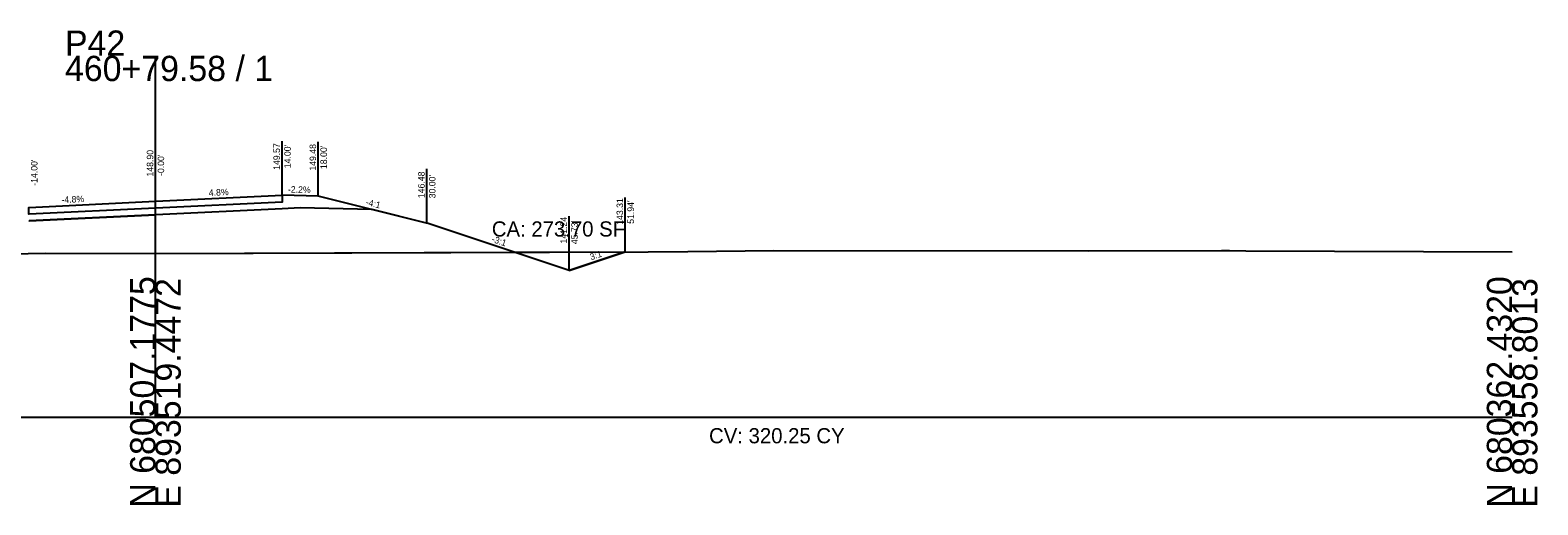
# Model space of a CAD drawing. Extents: x -26 to 4403, y -13 to 9578.
# Drawn here: x 1236.1 to 1402.8, y 990.3 to 1042.8 of the extents above; entities that cross this region are included whole.
import ezdxf

# ---------------------------------------------------------------- set-up
doc = ezdxf.new("R2010")
doc.units = 0
for name, color, linetype in [('_CIVIL_CONSTRUCTION', 7, 'Continuous'), ('CONST_DCH', 7, 'Continuous'), ('CONST_LV3', 7, 'Continuous'), ('DTM_CORRIDOR', 7, 'Continuous'), ('DTM_TEMP_DROP', 7, 'Continuous'), ('DTM_X_GROUND', 7, 'Continuous'), ('SLOPE_STAKES_FILL', 7, 'Continuous'), ('XS_CELL', 7, 'Continuous'), ('XS_M_SHAPES_EARTHWORK', 7, 'Continuous'), ('XS_P_ASPHALT', 7, 'Continuous'), ('XS_P_GROUND', 7, 'Continuous'), ('XS_P_SHOULDER', 7, 'Continuous'), ('XS_P_SUBGRADE_GRANULAR', 7, 'Continuous'), ('XS_P_TX_CLEARZONE', 7, 'Continuous'), ('XS_P_TX_FS_BS', 7, 'Continuous'), ('XS_SHEET_EW_TX_AREA', 7, 'Continuous'), ('XS_SHEET_EW_TX_VOLUME', 7, 'Continuous')]:
    doc.layers.add(name, color=color, linetype=linetype)

msp = doc.modelspace()

# ---------------------------------------------------------------- linework, layer by layer
at = {"layer": 'CONST_LV3'}
msp.add_lwpolyline([(1280, 1021.48), (1279.98, 1021.49), (1273.96, 1022.99)], dxfattribs=at)
at = {"layer": 'DTM_X_GROUND'}
msp.add_lwpolyline([(1205.86, 1017.54), (1237.81, 1018.17), (1249.9, 1018.11), (1304.48, 1018.32), (1308.85, 1018.36), (1318.36, 1018.46), (1353.16, 1018.41), (1367.85, 1018.45), (1368.76, 1018.44), (1370.55, 1018.43), (1400, 1018.3)], dxfattribs=at)
at = {"layer": 'XS_CELL'}
for p, q in [((1250, 1000), (1250, 1040)), ((1000, 1000), (1250, 1000)), ((1250, 1000), (1400, 1000))]:
    msp.add_line(p, q, dxfattribs=at)
at = {"layer": 'XS_M_SHAPES_EARTHWORK'}
msp.add_lwpolyline([(1205.86, 1017.54), (1237.81, 1018.17), (1249.9, 1018.11), (1289.67, 1018.26), (1280.04, 1021.47), (1280, 1021.48), (1279.98, 1021.49), (1279.97, 1021.49), (1273.96, 1022.99), (1273.94, 1022.99), (1266, 1023.17), (1264.01, 1023.07), (1264, 1023.07), (1250.04, 1022.4), (1250, 1022.4), (1236.04, 1021.73)], dxfattribs=at)
msp.add_lwpolyline([(1289.67, 1018.26), (1301.94, 1018.31), (1295.73, 1016.24)], close=True, dxfattribs=at)
at = {"layer": 'XS_P_ASPHALT'}
msp.add_lwpolyline([(1236.04, 1023.23), (1250, 1023.9), (1250.04, 1023.9), (1264, 1024.57), (1264, 1023.82), (1264, 1023.82), (1250.04, 1023.15), (1250, 1023.15), (1236.04, 1022.48), (1236, 1022.48), (1236, 1022.48), (1236, 1023.23), (1236.04, 1023.23)], dxfattribs=at)
at = {"layer": 'XS_P_GROUND'}
for points in [[(1295.73, 1016.24), (1280.04, 1021.47), (1280, 1021.48), (1279.97, 1021.49), (1268, 1024.48)], [(1295.73, 1016.24), (1301.94, 1018.31)]]:
    msp.add_lwpolyline(points, dxfattribs=at)
at = {"layer": 'XS_P_SHOULDER'}
msp.add_lwpolyline([(1268, 1024.48), (1267.99, 1024.48), (1264, 1024.57)], dxfattribs=at)
at = {"layer": 'XS_P_SUBGRADE_GRANULAR'}
for points in [[(1236, 1021.73), (1236.04, 1021.73), (1250, 1022.4)], [(1264, 1023.07), (1250.04, 1022.4), (1250, 1022.4)], [(1273.96, 1022.99), (1273.94, 1022.99), (1266, 1023.17), (1264.01, 1023.07), (1264, 1023.07)]]:
    msp.add_lwpolyline(points, dxfattribs=at)
at = {"layer": 'XS_P_TX_CLEARZONE'}
for p, q in [((1264, 1024.57), (1264, 1030.57)), ((1264, 1024.57), (1264, 1030.57)), ((1264, 1024.57), (1264, 1030.57)), ((1264, 1024.57), (1264, 1030.57)), ((1264, 1024.57), (1264, 1030.57)), ((1264, 1024.57), (1264, 1030.57)), ((1268, 1024.48), (1268, 1030.48)), ((1268, 1024.48), (1268, 1030.48)), ((1268, 1024.48), (1268, 1030.48)), ((1268, 1024.48), (1268, 1030.48)), ((1268, 1024.48), (1268, 1030.48)), ((1268, 1024.48), (1268, 1030.48)), ((1250, 1023.9), (1250, 1029.9)), ((1250, 1023.9), (1250, 1029.9)), ((1250, 1023.9), (1250, 1029.9)), ((1250, 1023.9), (1250, 1029.9)), ((1250, 1023.9), (1250, 1029.9)), ((1250, 1023.9), (1250, 1029.9)), ((1280, 1021.48), (1280, 1027.48)), ((1280, 1021.48), (1280, 1027.48)), ((1280, 1021.48), (1280, 1027.48)), ((1301.94, 1018.31), (1301.94, 1024.31)), ((1301.94, 1018.31), (1301.94, 1024.31)), ((1301.94, 1018.31), (1301.94, 1024.31)), ((1301.94, 1018.31), (1301.94, 1024.31)), ((1301.94, 1018.31), (1301.94, 1024.31)), ((1301.94, 1018.31), (1301.94, 1024.31)), ((1295.73, 1016.24), (1295.73, 1022.24)), ((1295.73, 1016.24), (1295.73, 1022.24)), ((1295.73, 1016.24), (1295.73, 1022.24)), ((1295.73, 1016.24), (1295.73, 1022.24)), ((1295.73, 1016.24), (1295.73, 1022.24)), ((1295.73, 1016.24), (1295.73, 1022.24))]:
    msp.add_line(p, q, dxfattribs=at)

# ---------------------------------------------------------------- texts
at = {"layer": '_CIVIL_CONSTRUCTION'}
for p in [(1249.96, 1023.84), (1263.96, 1024.51)]:
    msp.add_text('X', height=0.12, dxfattribs=at).set_placement(p)
at = {"layer": 'CONST_DCH'}
msp.add_text('X', height=0.12, dxfattribs=at).set_placement((1295.69, 1016.18))
at = {"layer": 'DTM_CORRIDOR'}
msp.add_text('X', height=0.12, dxfattribs=at).set_placement((1301.9, 1018.25))
at = {"layer": 'DTM_TEMP_DROP'}
msp.add_text('X', height=0.12, dxfattribs=at).set_placement((1267.96, 1024.42))
at = {"layer": 'SLOPE_STAKES_FILL'}
msp.add_text('X', height=0.12, dxfattribs=at).set_placement((1279.96, 1021.42))
at = {"layer": 'XS_CELL'}
for s, p in [('P42', (1240, 1040)), ('460+79.58 / 1', (1240, 1037.2))]:
    msp.add_text(s, height=2.8, dxfattribs=at).set_placement(p)
for s, p in [('N 680507.1775', (1250, 990)), ('E 893519.4472', (1252.8, 990)), ('N 680362.4320', (1400, 990)), ('E 893558.8013', (1402.8, 990))]:
    msp.add_text(s, height=2.8, rotation=90, dxfattribs=at).set_placement(p)
at = {"layer": 'XS_P_TX_CLEARZONE'}
for s, p in [('149.57', (1263.76, 1027.38)), ('149.57', (1263.76, 1027.38)), ('149.57', (1263.76, 1027.38)), ('149.57', (1263.76, 1027.38)), ('149.57', (1263.76, 1027.38)), ('149.57', (1263.76, 1027.38)), ('149.48', (1267.76, 1027.29)), ('149.48', (1267.76, 1027.29)), ('149.48', (1267.76, 1027.29)), ('149.48', (1267.76, 1027.29)), ('149.48', (1267.76, 1027.29)), ('149.48', (1267.76, 1027.29)), ('148.90', (1249.76, 1026.64)), ('148.90', (1249.76, 1026.64)), ('148.90', (1249.76, 1026.64)), ('148.90', (1249.76, 1026.64)), ('148.90', (1249.76, 1026.64)), ('148.90', (1249.76, 1026.64)), ("-0.00'", (1250.96, 1026.7)), ("-0.00'", (1250.96, 1026.7)), ("-0.00'", (1250.96, 1026.7)), ("-0.00'", (1250.96, 1026.7)), ("-0.00'", (1250.96, 1026.7)), ("-0.00'", (1250.96, 1026.7)), ("14.00'", (1264.96, 1027.56)), ("14.00'", (1264.96, 1027.56)), ("14.00'", (1264.96, 1027.56)), ("14.00'", (1264.96, 1027.56)), ("14.00'", (1264.96, 1027.56)), ("14.00'", (1264.96, 1027.56)), ("18.00'", (1268.96, 1027.47)), ("18.00'", (1268.96, 1027.47)), ("18.00'", (1268.96, 1027.47)), ("18.00'", (1268.96, 1027.47)), ("18.00'", (1268.96, 1027.47)), ("18.00'", (1268.96, 1027.47)), ("-14.00'", (1236.96, 1025.62)), ("-14.00'", (1236.96, 1025.62)), ("-14.00'", (1236.96, 1025.62)), ("-14.00'", (1236.96, 1025.62)), ("-14.00'", (1236.96, 1025.62)), ("-14.00'", (1236.96, 1025.62)), ('146.48', (1279.76, 1024.25)), ('146.48', (1279.76, 1024.25)), ('146.48', (1279.76, 1024.25)), ("30.00'", (1280.96, 1024.23)), ("30.00'", (1280.96, 1024.23)), ("30.00'", (1280.96, 1024.23)), ('143.31', (1301.7, 1021.3)), ('143.31', (1301.7, 1021.3)), ('143.31', (1301.7, 1021.3)), ('143.31', (1301.7, 1021.3)), ('143.31', (1301.7, 1021.3)), ('143.31', (1301.7, 1021.3)), ("51.94'", (1302.9, 1021.41)), ("51.94'", (1302.9, 1021.41)), ("51.94'", (1302.9, 1021.41)), ("51.94'", (1302.9, 1021.41)), ("51.94'", (1302.9, 1021.41)), ("51.94'", (1302.9, 1021.41)), ('141.24', (1295.49, 1019.23)), ('141.24', (1295.49, 1019.23)), ('141.24', (1295.49, 1019.23)), ('141.24', (1295.49, 1019.23)), ('141.24', (1295.49, 1019.23)), ('141.24', (1295.49, 1019.23)), ("45.73'", (1296.69, 1019.16)), ("45.73'", (1296.69, 1019.16)), ("45.73'", (1296.69, 1019.16)), ("45.73'", (1296.69, 1019.16)), ("45.73'", (1296.69, 1019.16)), ("45.73'", (1296.69, 1019.16))]:
    msp.add_text(s, height=0.72, rotation=90, dxfattribs=at).set_placement(p)
at = {"layer": 'XS_P_TX_FS_BS'}
for s, rotation, p in [('4.8%', 2.7481, (1255.91, 1024.48)), ('4.8%', 2.7481, (1255.91, 1024.48)), ('4.8%', 2.7481, (1255.91, 1024.48)), ('-2.2%', 358.7397, (1264.64, 1024.86)), ('-2.2%', 358.7397, (1264.64, 1024.86)), ('-2.2%', 358.7397, (1264.64, 1024.86)), ('-4.8%', 2.7481, (1239.62, 1023.7)), ('-4.8%', 2.7481, (1239.62, 1023.7)), ('-4.8%', 2.7481, (1239.62, 1023.7)), ('-4:1', 345.9638, (1273.19, 1023.5)), ('-4:1', 345.9638, (1273.19, 1023.5)), ('-4:1', 345.9638, (1273.19, 1023.5)), ('-3:1', 341.5668, (1287.1, 1019.43)), ('-3:1', 341.5668, (1287.1, 1019.43)), ('-3:1', 341.5668, (1287.1, 1019.43)), ('3:1', 18.4349, (1298.16, 1017.37)), ('3:1', 18.4349, (1298.16, 1017.37)), ('3:1', 18.4349, (1298.16, 1017.37))]:
    msp.add_text(s, height=0.72, rotation=rotation, dxfattribs=at).set_placement(p)
at = {"layer": 'XS_SHEET_EW_TX_AREA'}
msp.add_text('CA: 273.70 SF', height=1.68, dxfattribs=at).set_placement((1287.19, 1020))
at = {"layer": 'XS_SHEET_EW_TX_VOLUME'}
msp.add_text('CV: 320.25 CY', height=1.68, dxfattribs=at).set_placement((1311.21, 997.12))

doc.saveas('drawing.dxf')
